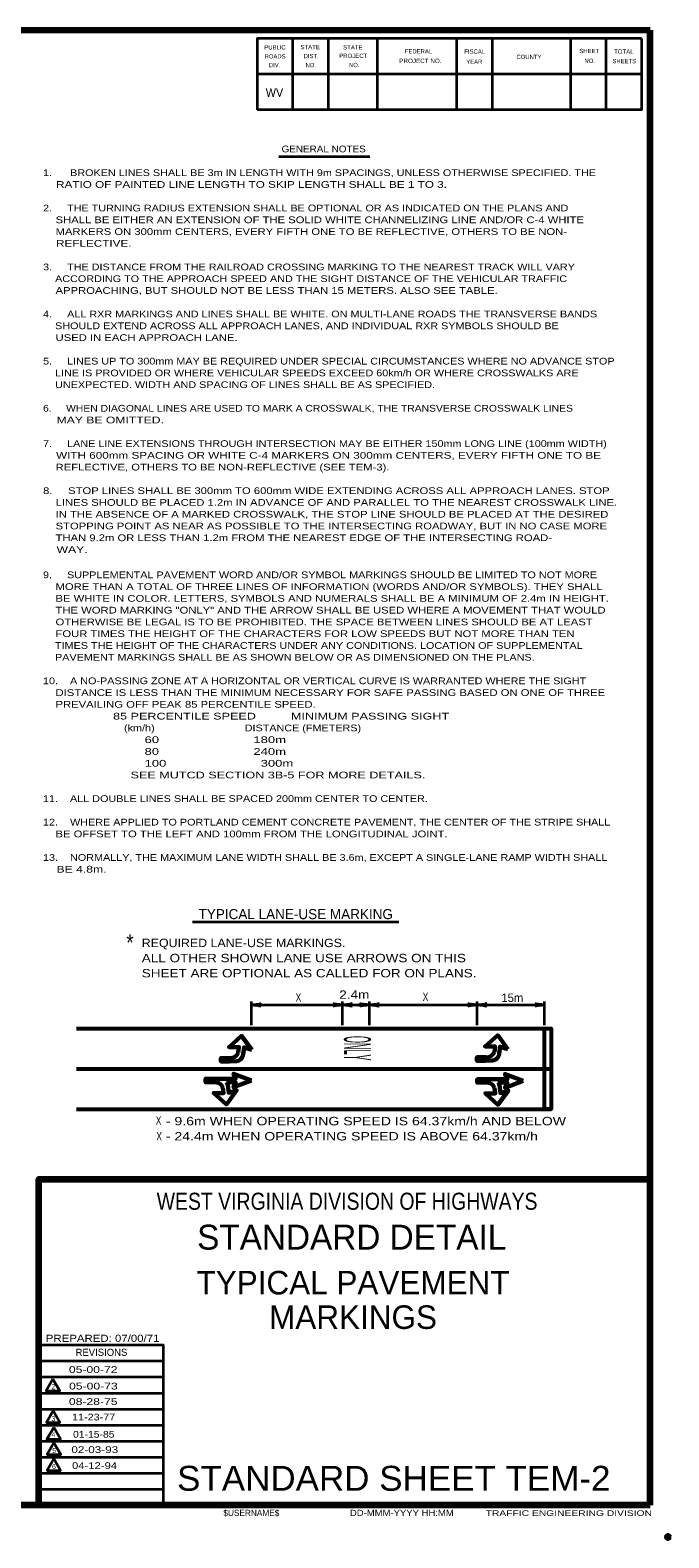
# Model space of a CAD drawing. Extents: x -90 to 765, y -1136 to -592.
# Drawn here: x 538 to 765, y -1136 to -598 of the extents above; entities that cross this region are included whole.
import ezdxf
from ezdxf.enums import TextEntityAlignment as Align

# ---------------------------------------------------------------- set-up
doc = ezdxf.new("R2010")
doc.units = 0
doc.header["$LTSCALE"] = 1.2
doc.header["$PDMODE"] = 32
doc.header["$PDSIZE"] = 0.6
doc.layers.add('1', color=7, linetype='Continuous', lineweight=90)
doc.layers.add('61', color=7, linetype='Continuous', lineweight=35)

msp = doc.modelspace()

# ---------------------------------------------------------------- linework, layer by layer
at = {"layer": '1', "lineweight": 158}
for q in [(758.78, -598.088), (758.78, -1007.888), (-32.82, -1124.188)]:
    msp.add_line((758.78, -1124.188), q, dxfattribs=at)
at = {"layer": '1', "lineweight": 13}
msp.add_line((758.78, -1124.188), (758.78, -598.088), dxfattribs=at)
at = {"layer": '1', "lineweight": 35}
for p, q in [((626.387, -643.108), (658.807, -643.108)), ((595.577, -916.043), (669.071, -916.043)), ((616.652, -952.913), (616.652, -944.513)), ((649.052, -952.913), (649.052, -944.513)), ((658.652, -952.913), (658.652, -944.513)), ((697.052, -952.913), (697.052, -944.513)), ((721.052, -952.913), (721.052, -944.513)), ((585.28, -1072.788), (540.78, -1072.788)), ((585.28, -1078.488), (540.78, -1078.488)), ((585.28, -1084.288), (540.78, -1084.288)), ((585.28, -1089.988), (540.78, -1089.988)), ((585.28, -1095.688), (540.78, -1095.688)), ((585.28, -1101.388), (540.78, -1101.388)), ((585.28, -1107.088), (540.78, -1107.088)), ((585.28, -1112.788), (540.78, -1112.788)), ((585.28, -1118.488), (540.78, -1118.488))]:
    msp.add_line(p, q, dxfattribs=at)
at = {"layer": '1', "lineweight": 53}
for p, q in [((554.252, -954.113), (723.452, -954.113)), ((554.252, -968.513), (723.452, -968.513)), ((554.252, -982.913), (723.452, -982.913))]:
    msp.add_line(p, q, dxfattribs=at)
at = {"layer": '1', "lineweight": 158}
for points in [[(758.78, -598.088), (-32.92, -598.188), (-32.82, -1124.188)], [(540.78, -1124.188), (540.78, -1007.888), (758.78, -1007.888)]]:
    msp.add_lwpolyline(points, dxfattribs=at)
at = {"layer": '1', "lineweight": 35}
for points in [[(616.652, -945.713), (649.052, -945.713), (658.652, -945.713), (697.052, -945.713), (721.052, -945.713)], [(585.28, -1124.188), (585.28, -1067.088), (540.78, -1067.088)]]:
    msp.add_lwpolyline(points, dxfattribs=at)
at = {"layer": '1', "lineweight": 60}
for points in [[(616.743, -961.757), (613.098, -956.775), (608.602, -960.785), (612.125, -960.785), (611.883, -962.729)], [(708.037, -961.502), (704.392, -956.52), (699.896, -960.53), (703.42, -960.53), (703.177, -962.474)], [(613.584, -963.458), (613.948, -960.906), (616.743, -961.757)], [(704.878, -963.203), (705.242, -960.651), (708.037, -961.502)], [(608.724, -964.673), (605.686, -964.673), (605.686, -965.888), (608.724, -965.888), (611.275, -965.766)], [(700.018, -964.418), (696.98, -964.418), (696.98, -965.633), (700.018, -965.633), (702.569, -965.511)], [(600.233, -972.078), (610.925, -972.078), (610.196, -970.256), (616.635, -972.686)], [(603.27, -973.293), (600.233, -973.293), (600.233, -972.078), (603.27, -972.078)], [(616.635, -972.686), (610.196, -975.116), (610.925, -973.293), (607.644, -973.293)], [(697.063, -972.206), (707.755, -972.206), (707.026, -970.383), (713.466, -972.813)], [(700.101, -973.421), (697.063, -973.421), (697.063, -972.206), (700.101, -972.206)], [(713.466, -972.813), (707.026, -975.243), (707.755, -973.421), (704.475, -973.421)], [(608.13, -974.265), (608.495, -977.06), (611.289, -976.209), (607.644, -981.191), (603.149, -977.181), (606.672, -977.181), (606.429, -975.237)], [(704.961, -974.393), (705.325, -977.187), (708.12, -976.337), (704.475, -981.318), (699.979, -977.309), (703.503, -977.309), (703.26, -975.365)]]:
    msp.add_lwpolyline(points, dxfattribs=at)
at = {"layer": '1', "lineweight": 53}
msp.add_lwpolyline([(721.052, -982.913), (721.052, -954.113), (723.452, -954.113), (723.452, -982.913)], close=True, dxfattribs=at)
at = {"layer": '1', "lineweight": 35}
for points in [[(545.823, -1079.225), (543.423, -1083.382), (548.223, -1083.382)], [(545.902, -1090.54), (543.502, -1094.697), (548.302, -1094.697)], [(546.09, -1096.396), (543.69, -1100.553), (548.49, -1100.553)], [(546.199, -1101.944), (543.799, -1106.101), (548.599, -1106.101)], [(546.12, -1107.641), (543.72, -1111.798), (548.52, -1111.798)]]:
    msp.add_lwpolyline(points, close=True, dxfattribs=at)
at = {"layer": '1', "lineweight": 60}
for centre, radius, start, end in [((700.308, -961.351), 3.08, 264.58762, 338.62739), ((702.292, -962.904), 2.622, 276.08048, 9.44985), ((609.014, -961.606), 3.08, 264.58762, 338.62739), ((610.997, -963.159), 2.622, 276.08048, 9.44985), ((603.561, -976.36), 3.08, 21.37261, 95.41238), ((605.544, -974.807), 2.622, 11.82663, 35.26036), ((700.391, -976.487), 3.08, 21.37261, 95.41238), ((702.375, -974.934), 2.622, 11.82663, 35.26036)]:
    msp.add_arc(centre, radius, start, end, dxfattribs=at)
at = {"layer": '1', "lineweight": 40}
for centre, major_axis, ratio, start_param, end_param in [((617.996, -945.967), (-2.108, 0.211), 0.07063, 3.1407148, 5.41811), ((617.996, -945.967), (-2.108, 0.211), 0.07063, 3.1407148, 5.41811), ((617.961, -945.382), (-2.143, -0.187), 0.122415, 0.8963533, 3.1415927), ((617.961, -945.382), (-2.143, -0.187), 0.122415, 0.8963533, 3.1415927), ((647.742, -946.045), (2.143, 0.187), 0.122415, 0.8963533, 3.1415927), ((647.742, -946.045), (2.143, 0.187), 0.122415, 0.8963533, 3.1415927), ((647.707, -945.459), (2.108, -0.211), 0.07063, 3.1407148, 5.41811), ((647.707, -945.459), (2.108, -0.211), 0.07063, 3.1407148, 5.41811), ((650.396, -945.967), (-2.108, 0.211), 0.07063, 3.1407148, 5.41811), ((650.361, -945.382), (-2.143, -0.187), 0.122415, 0.8963533, 3.1415927), ((657.342, -946.045), (2.143, 0.187), 0.122415, 0.8963533, 3.1415927), ((657.342, -946.045), (2.143, 0.187), 0.122415, 0.8963533, 3.1415927), ((657.307, -945.459), (2.108, -0.211), 0.07063, 3.1407148, 5.41811), ((657.307, -945.459), (2.108, -0.211), 0.07063, 3.1407148, 5.41811), ((659.996, -945.967), (-2.108, 0.211), 0.07063, 3.1407148, 5.41811), ((659.996, -945.967), (-2.108, 0.211), 0.07063, 3.1407148, 5.41811), ((659.961, -945.382), (-2.143, -0.187), 0.122415, 0.8963533, 3.1415927), ((659.961, -945.382), (-2.143, -0.187), 0.122415, 0.8963533, 3.1415927), ((695.742, -946.045), (2.143, 0.187), 0.122415, 0.8963533, 3.1415927), ((695.742, -946.045), (2.143, 0.187), 0.122415, 0.8963533, 3.1415927), ((695.707, -945.459), (2.108, -0.211), 0.07063, 3.1407148, 5.41811), ((695.707, -945.459), (2.108, -0.211), 0.07063, 3.1407148, 5.41811), ((698.396, -945.967), (-2.108, 0.211), 0.07063, 3.1407148, 5.41811), ((698.396, -945.967), (-2.108, 0.211), 0.07063, 3.1407148, 5.41811), ((698.361, -945.382), (-2.143, -0.187), 0.122415, 0.8963533, 3.1415927), ((698.361, -945.382), (-2.143, -0.187), 0.122415, 0.8963533, 3.1415927), ((719.742, -946.045), (2.143, 0.187), 0.122415, 0.8963533, 3.1415927), ((719.707, -945.459), (2.108, -0.211), 0.07063, 3.1407148, 5.41811)]:
    msp.add_ellipse(centre, major_axis=major_axis, ratio=ratio, start_param=start_param, end_param=end_param, dxfattribs=at)
at = {"layer": '1'}
msp.add_point((765.08, -1135.488), dxfattribs=at)
at = {"layer": '61'}
for p, q in [((631.28, -601.088), (631.28, -626.488)), ((643.98, -601.088), (643.98, -626.488)), ((661.38, -601.088), (661.38, -626.488)), ((689.68, -601.088), (689.68, -626.488)), ((702.38, -601.088), (702.38, -626.488)), ((730.28, -601.088), (730.28, -626.488)), ((742.98, -601.088), (742.98, -626.488)), ((755.68, -613.788), (618.58, -613.788))]:
    msp.add_line(p, q, dxfattribs=at)
at = {"layer": '61', "lineweight": 53}
for q in [(606.08, -1124.188), (606.08, -1124.188), (606.08, -1124.188), (606.38, -1124.188), (606.38, -1124.188)]:
    msp.add_line((758.78, -1124.188), q, dxfattribs=at)
at = {"layer": '61'}
for points in [[(755.68, -601.088), (618.58, -601.088), (618.58, -626.488)], [(755.68, -601.088), (755.68, -626.488), (618.58, -626.488)]]:
    msp.add_lwpolyline(points, dxfattribs=at)

# ---------------------------------------------------------------- texts
at = {"layer": '1'}
for s, height, width, p in [('WV', 3.048, 0.95, (621.68, -621.888)), ('1.      BROKEN LINES SHALL BE 3m IN LENGTH WITH 9m SPACINGS, UNLESS OTHERWISE SPECIFIED. THE', 2.4, 1.2, (542.306, -650.129)), ('    RATIO OF PAINTED LINE LENGTH TO SKIP LENGTH SHALL BE 1 TO 3.', 2.4, 1.3, (542.306, -654.329)), ('2.     THE TURNING RADIUS EXTENSION SHALL BE OPTIONAL OR AS INDICATED ON THE PLANS AND', 2.4, 1.2, (542.306, -662.729)), ('    SHALL BE EITHER AN EXTENSION OF THE SOLID WHITE CHANNELIZING LINE AND/OR C-4 WHITE', 2.4, 1.25, (542.306, -666.929)), ('    MARKERS ON 300mm CENTERS, EVERY FIFTH ONE TO BE REFLECTIVE, OTHERS TO BE NON-', 2.4, 1.25, (542.306, -671.129)), ('    REFLECTIVE.', 2.4, 1.3, (542.306, -675.329)), ('3.     THE DISTANCE FROM THE RAILROAD CROSSING MARKING TO THE NEAREST TRACK WILL VARY', 2.4, 1.2, (542.306, -683.729)), ('    ACCORDING TO THE APPROACH SPEED AND THE SIGHT DISTANCE OF THE VEHICULAR TRAFFIC', 2.4, 1.2, (542.306, -687.929)), ('    APPROACHING, BUT SHOULD NOT BE LESS THAN 15 METERS. ALSO SEE TABLE.', 2.4, 1.25, (542.306, -692.129)), ('4.     ALL RXR MARKINGS AND LINES SHALL BE WHITE. ON MULTI-LANE ROADS THE TRANSVERSE BANDS', 2.4, 1.2, (542.306, -700.529)), ('    SHOULD EXTEND ACROSS ALL APPROACH LANES, AND INDIVIDUAL RXR SYMBOLS SHOULD BE', 2.4, 1.2, (542.306, -704.729)), ('    USED IN EACH APPROACH LANE.', 2.4, 1.25, (542.306, -708.929)), ('5.     LINES UP TO 300mm MAY BE REQUIRED UNDER SPECIAL CIRCUMSTANCES WHERE NO ADVANCE STOP', 2.4, 1.2, (542.306, -717.329)), ('    LINE IS PROVIDED OR WHERE VEHICULAR SPEEDS EXCEED 60km/h OR WHERE CROSSWALKS ARE', 2.4, 1.2, (542.306, -721.529)), ('    UNEXPECTED. WIDTH AND SPACING OF LINES SHALL BE AS SPECIFIED.', 2.4, 1.2, (542.306, -725.729)), ('6.     WHEN DIAGONAL LINES ARE USED TO MARK A CROSSWALK, THE TRANSVERSE CROSSWALK LINES', 2.4, 1.15, (542.306, -734.129)), ('    MAY BE OMITTED.', 2.4, 1.35, (542.306, -738.329)), ('7.     LANE LINE EXTENSIONS THROUGH INTERSECTION MAY BE EITHER 150mm LONG LINE (100mm WIDTH)', 2.4, 1.2, (542.306, -746.729)), ('    WITH 600mm SPACING OR WHITE C-4 MARKERS ON 300mm CENTERS, EVERY FIFTH ONE TO BE', 2.4, 1.3, (542.306, -750.929)), ('    REFLECTIVE, OTHERS TO BE NON-REFLECTIVE (SEE TEM-3).', 2.4, 1.25, (542.306, -755.129)), ('8.     STOP LINES SHALL BE 300mm TO 600mm WIDE EXTENDING ACROSS ALL APPROACH LANES. STOP', 2.4, 1.25, (542.306, -763.529)), ('    LINES SHOULD BE PLACED 1.2m IN ADVANCE OF AND PARALLEL TO THE NEAREST CROSSWALK LINE.', 2.4, 1.25, (542.306, -767.729)), ('    STOPPING POINT AS NEAR AS POSSIBLE TO THE INTERSECTING ROADWAY, BUT IN NO CASE MORE', 2.4, 1.25, (542.306, -776.129)), ('    IN THE ABSENCE OF A MARKED CROSSWALK, THE STOP LINE SHOULD BE PLACED AT THE DESIRED', 2.4, 1.25, (542.306, -771.929)), ('    THAN 9.2m OR LESS THAN 1.2m FROM THE NEAREST EDGE OF THE INTERSECTING ROAD-', 2.4, 1.25, (542.306, -780.329)), ('    WAY.', 2.4, 1.35, (542.306, -784.529)), ('9.     SUPPLEMENTAL PAVEMENT WORD AND/OR SYMBOL MARKINGS SHOULD BE LIMITED TO NOT MORE', 2.4, 1.2, (542.283, -793.541)), ('    MORE THAN A TOTAL OF THREE LINES OF INFORMATION (WORDS AND/OR SYMBOLS). THEY SHALL', 2.4, 1.25, (542.283, -797.741)), ('    BE WHITE IN COLOR. LETTERS, SYMBOLS AND NUMERALS SHALL BE A MINIMUM OF 2.4m IN HEIGHT.', 2.4, 1.25, (542.283, -801.941)), ('    THE WORD MARKING "ONLY" AND THE ARROW SHALL BE USED WHERE A MOVEMENT THAT WOULD', 2.4, 1.25, (542.283, -806.141)), ('    OTHERWISE BE LEGAL IS TO BE PROHIBITED. THE SPACE BETWEEN LINES SHOULD BE AT LEAST', 2.4, 1.25, (542.283, -810.341)), ('    TIMES THE HEIGHT OF THE CHARACTERS UNDER ANY CONDITIONS. LOCATION OF SUPPLEMENTAL', 2.4, 1.2, (542.283, -818.741)), ('    FOUR TIMES THE HEIGHT OF THE CHARACTERS FOR LOW SPEEDS BUT NOT MORE THAN TEN', 2.4, 1.25, (542.283, -814.541)), ('    PAVEMENT MARKINGS SHALL BE AS SHOWN BELOW OR AS DIMENSIONED ON THE PLANS.', 2.4, 1.2, (542.283, -822.941)), ('10.    A NO-PASSING ZONE AT A HORIZONTAL OR VERTICAL CURVE IS WARRANTED WHERE THE SIGHT', 2.4, 1.2, (542.283, -831.341)), ('    DISTANCE IS LESS THAN THE MINIMUM NECESSARY FOR SAFE PASSING BASED ON ONE OF THREE', 2.4, 1.25, (542.283, -835.541)), ('    PREVAILING OFF PEAK 85 PERCENTILE SPEED.', 2.4, 1.25, (542.283, -839.741)), ('                    85 PERCENTILE SPEED          MINIMUM PASSING SIGHT', 2.4, 1.4, (542.283, -843.941)), ('                           (km/h)                              DISTANCE (FMETERS)', 2.4, 1.2, (542.283, -848.141)), ('                            80                          240m', 2.4, 1.45, (542.283, -856.541)), ('                            60                          180m', 2.4, 1.45, (542.283, -852.341)), ('                            100                          300m', 2.4, 1.45, (542.283, -860.741)), ('                         SEE MUTCD SECTION 3B-5 FOR MORE DETAILS.', 2.4, 1.4, (542.283, -864.941)), ('11.    ALL DOUBLE LINES SHALL BE SPACED 200mm CENTER TO CENTER.', 2.4, 1.2, (542.283, -873.341)), ('12.    WHERE APPLIED TO PORTLAND CEMENT CONCRETE PAVEMENT, THE CENTER OF THE STRIPE SHALL ', 2.4, 1.2, (542.283, -881.741)), ('    BE OFFSET TO THE LEFT AND 100mm FROM THE LONGITUDINAL JOINT.', 2.4, 1.25, (542.283, -885.941)), ('13.    NORMALLY, THE MAXIMUM LANE WIDTH SHALL BE 3.6m, EXCEPT A SINGLE-LANE RAMP WIDTH SHALL', 2.4, 1.2, (542.283, -894.341)), ('    BE 4.8m.', 2.4, 1.35, (542.283, -898.541)), ('REQUIRED LANE-USE MARKINGS.', 3, 1.1, (577.492, -925.108)), ('ALL OTHER SHOWN LANE USE ARROWS ON THIS', 3, 1.2, (577.492, -930.508)), ('SHEET ARE OPTIONAL AS CALLED FOR ON PLANS.', 3, 1.2, (577.492, -935.908)), ('- 9.6m WHEN OPERATING SPEED IS 64.37km/h AND BELOW', 3, 1.25, (586.064, -988.663)), ('- 24.4m WHEN OPERATING SPEED IS ABOVE 64.37km/h', 3, 1.25, (586.064, -994.063)), ('PREPARED: 07/00/71', 2.537, 1.2, (543.28, -1065.888)), ('2', 1.8, 0.9, (545.262, -1082.778)), ('3', 1.8, 0.9, (545.292, -1094.191)), ('4', 1.8, 0.95, (545.282, -1099.899)), ('5', 1.8, 0.9, (545.588, -1105.546)), ('6', 1.8, 0.85, (545.509, -1111.243)), ('STANDARD SHEET TEM-2 ', 8.881, 1.05, (590.08, -1118.988)), ('DD-MMM-YYYY HH:MM', 2.2, 1.15, (651.68, -1127.988)), ('TRAFFIC ENGINEERING DIVISION', 2.031, 1.35, (700.08, -1127.988))]:
    msp.add_text(s, height=height, dxfattribs=dict(at, width=width)).set_placement(p)
for s, height, width, p in [('GENERAL NOTES', 2.4, 1.1, (642.326, -641.651)), ('*', 6, 0.85, (573.303, -926.505)), ('2.4m', 3, 1.2, (653.261, -943.555)), ('X', 3, 0.75, (633.347, -944.561)), ('X', 3, 0.75, (678.63, -944.361)), ('X', 3, 0.75, (583.476, -988.461)), ('X', 3, 0.75, (583.676, -994.049)), ('WEST VIRGINIA DIVISION OF HIGHWAYS', 6.089, 0.85, (650.68, -1018.788)), ('05-00-72', 2.4, 1.35, (560.181, -1076.964)), ('05-00-73', 2.4, 1.35, (560.236, -1082.877)), ('08-28-75', 2.4, 1.35, (560.181, -1088.394)), ('11-23-77', 2.4, 1.2, (560.339, -1093.912)), ('01-15-85', 2.4, 1.15, (560.385, -1100.064)), ('02-03-93', 2.4, 1.3, (560.735, -1105.52)), ('04-12-94', 2.4, 1.25, (560.665, -1111.217))]:
    msp.add_text(s, height=height, dxfattribs=dict(at, width=width)).set_placement(p, align=Align.CENTER)
for s, height, p in [('TYPICAL LANE-USE MARKING', 3.6, (632.385, -915.132)), ('15m', 3, (709.581, -944.673)), ('STANDARD DETAIL', 8.881, (652.33, -1032.988)), ('TYPICAL PAVEMENT', 8.391, (652.797, -1048.975)), ('MARKINGS', 8.391, (652.797, -1061.276))]:
    msp.add_text(s, height=height, dxfattribs=at).set_placement(p, align=Align.CENTER)
at = {"layer": '1', "width": 0.25}
msp.add_text('ONLY', height=9.6, rotation=270, dxfattribs=at).set_placement((649.556, -961.168), align=Align.CENTER)
at = {"layer": '1'}
for s, height, p in [('REVISIONS', 2.537, (553.88, -1070.888)), ('$USERNAME$', 2.2, (606.58, -1127.988))]:
    msp.add_text(s, height=height, dxfattribs=at).set_placement(p)
at = {"layer": '61'}
for s, height, rotation, p in [('PUBLIC', 1.525, 0.033, (621.18, -604.988)), ('ROADS', 1.525, 0.124, (621.28, -608.188)), ('DIST.', 1.525, 0.056, (635.18, -608.088)), ('FEDERAL', 1.523, 0.007, (671.28, -606.388)), ('FISCAL', 1.525, 359.942, (692.48, -606.488)), ('COUNTY', 1.523, 0.069, (711.08, -608.388)), ('SHEET', 1.525, 0.059, (733.48, -606.288)), ('DIV.', 1.525, 359.932, (622.78, -611.288)), ('YEAR', 1.523, 0.105, (693.18, -610.088)), ('SHEETS', 1.523, 359.959, (745.28, -609.888))]:
    msp.add_text(s, height=height, rotation=rotation, dxfattribs=at).set_placement(p)
for s, rotation, width, p in [('STATE', 0.059, 1.05, (634.08, -604.888)), ('PROJECT', 359.908, 1.05, (647.88, -607.988)), ('STATE', 0.059, 1.05, (649.28, -604.988)), ('TOTAL', 359.926, 1.05, (745.88, -606.488)), ('NO.', 359.852, 0.9, (635.88, -611.288)), ('NO.', 0.225, 0.9, (651.38, -611.288)), ('PROJECT NO.', 359.922, 1.1, (669.28, -609.788)), ('NO.', 359.852, 0.9, (735.28, -609.788))]:
    msp.add_text(s, height=1.525, rotation=rotation, dxfattribs=dict(at, width=width)).set_placement(p)

doc.saveas('drawing.dxf')
